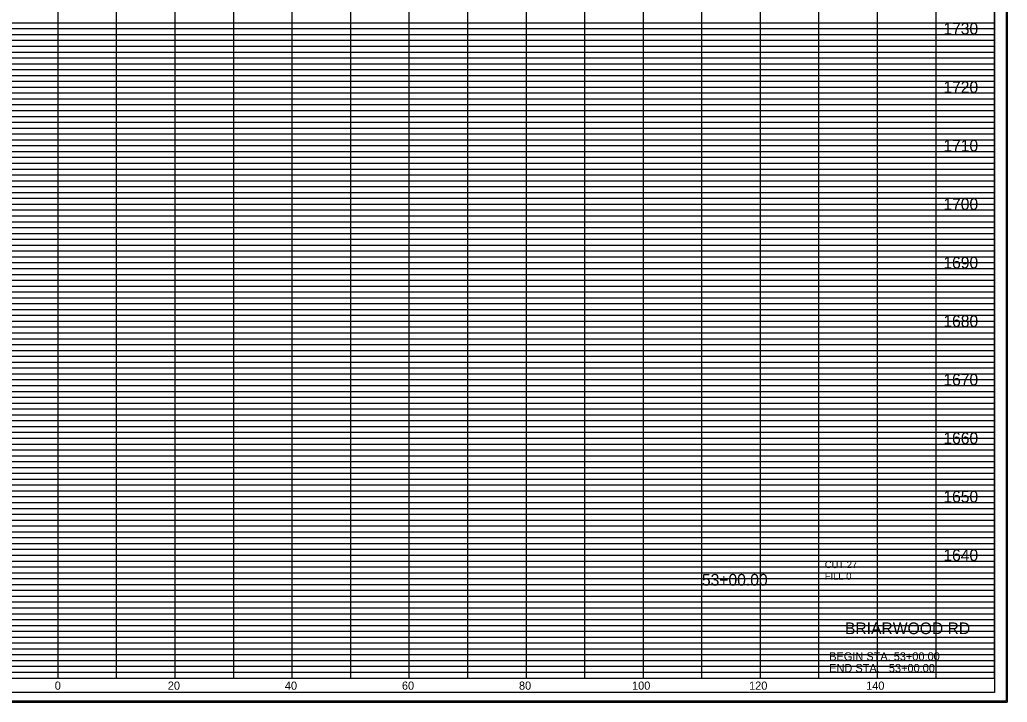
# Model space of a CAD drawing. Extents: x 980 to 2228, y 978 to 2394.
# Drawn here: x 1153.4 to 1322.2, y 1535.9 to 1652.5 of the extents above; entities that cross this region are included whole.
import ezdxf

# ---------------------------------------------------------------- set-up
doc = ezdxf.new("R2010")
doc.units = 0
for name, color, linetype in [('DESIGN - SHEET - Corner Text', 7, 'Continuous'), ('DESIGN - SHEET - Light Grid', 7, 'Continuous'), ('DESIGN - SHEET - Linework', 7, 'Continuous'), ('DESIGN - SHEET - Plot Shape', 7, 'Continuous'), ('DESIGN - TYPICAL - Finished Grade and Subgrade', 7, 'Continuous'), ('DESIGN - TYPICAL - Text', 7, 'Continuous')]:
    doc.layers.add(name, color=color, linetype=linetype)

# ---------------------------------------------------------------- blocks, each defined once
blk = doc.blocks.new('XSTSHT')
at = {"layer": 'DESIGN - SHEET - Light Grid'}
for p, q in [((8, 11.2), (16, 11.2)), ((16, 11.2), (24, 11.2)), ((24, 11.2), (32, 11.2)), ((8, 11.1), (16, 11.1)), ((16, 11.1), (24, 11.1)), ((24, 11.1), (32, 11.1)), ((8, 10.9), (16, 10.9)), ((8, 10.8), (16, 10.8)), ((16, 10.9), (24, 10.9)), ((16, 10.8), (24, 10.8)), ((24, 10.9), (32, 10.9)), ((24, 10.8), (32, 10.8)), ((8, 10.7), (16, 10.7)), ((16, 10.7), (24, 10.7)), ((24, 10.7), (32, 10.7)), ((8, 10.6), (16, 10.6)), ((8, 10.5), (16, 10.5)), ((16, 10.6), (24, 10.6)), ((16, 10.5), (24, 10.5)), ((24, 10.6), (32, 10.6)), ((24, 10.5), (32, 10.5)), ((8, 10.4), (16, 10.4)), ((8, 10.3), (16, 10.3)), ((16, 10.4), (24, 10.4)), ((16, 10.3), (24, 10.3)), ((24, 10.4), (32, 10.4)), ((24, 10.3), (32, 10.3)), ((8, 10.2), (16, 10.2)), ((16, 10.2), (24, 10.2)), ((24, 10.2), (32, 10.2)), ((8, 10.1), (16, 10.1)), ((16, 10.1), (24, 10.1)), ((24, 10.1), (32, 10.1)), ((8, 9.9), (16, 9.9)), ((8, 9.8), (16, 9.8)), ((16, 9.9), (24, 9.9)), ((16, 9.8), (24, 9.8)), ((24, 9.9), (32, 9.9)), ((24, 9.8), (32, 9.8)), ((8, 9.7), (16, 9.7)), ((16, 9.7), (24, 9.7)), ((24, 9.7), (32, 9.7)), ((8, 9.6), (16, 9.6)), ((8, 9.5), (16, 9.5)), ((16, 9.6), (24, 9.6)), ((16, 9.5), (24, 9.5)), ((24, 9.6), (32, 9.6)), ((24, 9.5), (32, 9.5)), ((8, 9.4), (16, 9.4)), ((8, 9.3), (16, 9.3)), ((16, 9.4), (24, 9.4)), ((16, 9.3), (24, 9.3)), ((24, 9.4), (32, 9.4)), ((24, 9.3), (32, 9.3)), ((8, 9.2), (16, 9.2)), ((16, 9.2), (24, 9.2)), ((24, 9.2), (32, 9.2)), ((8, 9.1), (16, 9.1)), ((16, 9.1), (24, 9.1)), ((24, 9.1), (32, 9.1)), ((8, 8.9), (16, 8.9)), ((8, 8.8), (16, 8.8)), ((16, 8.9), (24, 8.9)), ((16, 8.8), (24, 8.8)), ((24, 8.9), (32, 8.9)), ((24, 8.8), (32, 8.8)), ((8, 8.7), (16, 8.7)), ((16, 8.7), (24, 8.7)), ((24, 8.7), (32, 8.7)), ((8, 8.6), (16, 8.6)), ((8, 8.5), (16, 8.5)), ((16, 8.6), (24, 8.6)), ((16, 8.5), (24, 8.5)), ((24, 8.6), (32, 8.6)), ((24, 8.5), (32, 8.5)), ((8, 8.4), (16, 8.4)), ((8, 8.3), (16, 8.3)), ((16, 8.4), (24, 8.4)), ((16, 8.3), (24, 8.3)), ((24, 8.4), (32, 8.4)), ((24, 8.3), (32, 8.3)), ((8, 8.2), (16, 8.2)), ((8, 8.1), (16, 8.1)), ((16, 8.2), (24, 8.2)), ((16, 8.1), (24, 8.1)), ((24, 8.2), (32, 8.2)), ((24, 8.1), (32, 8.1)), ((8, 7.9), (16, 7.9)), ((8, 7.8), (16, 7.8)), ((16, 7.9), (24, 7.9)), ((16, 7.8), (24, 7.8)), ((24, 7.9), (32, 7.9)), ((24, 7.8), (32, 7.8)), ((8, 7.7), (16, 7.7)), ((8, 7.6), (16, 7.6)), ((16, 7.7), (24, 7.7)), ((16, 7.6), (24, 7.6)), ((24, 7.7), (32, 7.7)), ((24, 7.6), (32, 7.6)), ((8, 7.5), (16, 7.5)), ((16, 7.5), (24, 7.5)), ((24, 7.5), (32, 7.5)), ((8, 7.4), (16, 7.4)), ((8, 7.3), (16, 7.3)), ((16, 7.4), (24, 7.4)), ((16, 7.3), (24, 7.3)), ((24, 7.4), (32, 7.4)), ((24, 7.3), (32, 7.3)), ((8, 7.2), (16, 7.2)), ((8, 7.1), (16, 7.1)), ((16, 7.2), (24, 7.2)), ((16, 7.1), (24, 7.1)), ((24, 7.2), (32, 7.2)), ((24, 7.1), (32, 7.1)), ((8, 6.9), (16, 6.9)), ((8, 6.8), (16, 6.8)), ((16, 6.9), (24, 6.9)), ((16, 6.8), (24, 6.8)), ((24, 6.9), (32, 6.9)), ((24, 6.8), (32, 6.8)), ((8, 6.7), (16, 6.7)), ((8, 6.6), (16, 6.6)), ((16, 6.7), (24, 6.7)), ((16, 6.6), (24, 6.6)), ((24, 6.7), (32, 6.7)), ((24, 6.6), (32, 6.6)), ((8, 6.5), (16, 6.5)), ((16, 6.5), (24, 6.5)), ((24, 6.5), (32, 6.5)), ((8, 6.4), (16, 6.4)), ((8, 6.3), (16, 6.3)), ((16, 6.4), (24, 6.4)), ((16, 6.3), (24, 6.3)), ((24, 6.4), (32, 6.4)), ((24, 6.3), (32, 6.3)), ((8, 6.2), (16, 6.2)), ((8, 6.1), (16, 6.1)), ((16, 6.2), (24, 6.2)), ((16, 6.1), (24, 6.1)), ((24, 6.2), (32, 6.2)), ((24, 6.1), (32, 6.1)), ((8, 5.9), (16, 5.9)), ((8, 5.8), (16, 5.8)), ((16, 5.9), (24, 5.9)), ((16, 5.8), (24, 5.8)), ((24, 5.9), (32, 5.9)), ((24, 5.8), (32, 5.8)), ((8, 5.7), (16, 5.7)), ((8, 5.6), (16, 5.6)), ((16, 5.7), (24, 5.7)), ((16, 5.6), (24, 5.6)), ((24, 5.7), (32, 5.7)), ((24, 5.6), (32, 5.6)), ((8, 5.5), (16, 5.5)), ((8, 5.4), (16, 5.4)), ((16, 5.5), (24, 5.5)), ((16, 5.4), (24, 5.4)), ((24, 5.5), (32, 5.5)), ((24, 5.4), (32, 5.4)), ((8, 5.3), (16, 5.3)), ((16, 5.3), (24, 5.3)), ((24, 5.3), (32, 5.3)), ((8, 5.2), (16, 5.2)), ((8, 5.1), (16, 5.1)), ((16, 5.2), (24, 5.2)), ((16, 5.1), (24, 5.1)), ((24, 5.2), (32, 5.2)), ((24, 5.1), (32, 5.1)), ((8, 4.9), (16, 4.9)), ((16, 4.9), (24, 4.9)), ((24, 4.9), (32, 4.9)), ((8, 4.8), (16, 4.8)), ((16, 4.8), (24, 4.8)), ((24, 4.8), (32, 4.8)), ((8, 4.7), (16, 4.7)), ((8, 4.6), (16, 4.6)), ((16, 4.7), (24, 4.7)), ((16, 4.6), (24, 4.6)), ((24, 4.7), (32, 4.7)), ((24, 4.6), (32, 4.6)), ((8, 4.5), (16, 4.5)), ((8, 4.4), (16, 4.4)), ((16, 4.5), (24, 4.5)), ((16, 4.4), (24, 4.4)), ((24, 4.5), (32, 4.5)), ((24, 4.4), (32, 4.4)), ((8, 4.3), (16, 4.3)), ((16, 4.3), (24, 4.3)), ((24, 4.3), (32, 4.3)), ((8, 4.2), (16, 4.2)), ((8, 4.1), (16, 4.1)), ((16, 4.2), (24, 4.2)), ((16, 4.1), (24, 4.1)), ((24, 4.2), (32, 4.2)), ((24, 4.1), (32, 4.1)), ((8, 3.9), (16, 3.9)), ((16, 3.9), (24, 3.9)), ((24, 3.9), (32, 3.9)), ((8, 3.8), (16, 3.8)), ((16, 3.8), (24, 3.8)), ((24, 3.8), (32, 3.8)), ((8, 3.7), (16, 3.7)), ((8, 3.6), (16, 3.6)), ((16, 3.7), (24, 3.7)), ((16, 3.6), (24, 3.6)), ((24, 3.7), (32, 3.7)), ((24, 3.6), (32, 3.6)), ((8, 3.5), (16, 3.5)), ((8, 3.4), (16, 3.4)), ((16, 3.5), (24, 3.5)), ((16, 3.4), (24, 3.4)), ((24, 3.5), (32, 3.5)), ((24, 3.4), (32, 3.4)), ((8, 3.3), (16, 3.3)), ((16, 3.3), (24, 3.3)), ((24, 3.3), (32, 3.3)), ((8, 3.2), (16, 3.2)), ((8, 3.1), (16, 3.1)), ((16, 3.2), (24, 3.2)), ((16, 3.1), (24, 3.1)), ((24, 3.2), (32, 3.2)), ((24, 3.1), (32, 3.1)), ((8, 2.9), (16, 2.9)), ((16, 2.9), (24, 2.9)), ((24, 2.9), (32, 2.9)), ((8, 2.8), (16, 2.8)), ((8, 2.7), (16, 2.7)), ((16, 2.8), (24, 2.8)), ((16, 2.7), (24, 2.7)), ((24, 2.8), (32, 2.8)), ((24, 2.7), (32, 2.7)), ((8, 2.6), (16, 2.6)), ((16, 2.6), (24, 2.6)), ((24, 2.6), (32, 2.6)), ((8, 2.5), (16, 2.5)), ((8, 2.4), (16, 2.4)), ((16, 2.5), (24, 2.5)), ((16, 2.4), (24, 2.4)), ((24, 2.5), (32, 2.5)), ((24, 2.4), (32, 2.4)), ((8, 2.3), (16, 2.3)), ((8, 2.2), (16, 2.2)), ((16, 2.3), (24, 2.3)), ((16, 2.2), (24, 2.2)), ((24, 2.3), (32, 2.3)), ((24, 2.2), (32, 2.2)), ((8, 2.1), (16, 2.1)), ((16, 2.1), (24, 2.1)), ((24, 2.1), (32, 2.1)), ((8, 1.9), (16, 1.9)), ((16, 1.9), (24, 1.9)), ((24, 1.9), (32, 1.9)), ((8, 1.8), (16, 1.8)), ((8, 1.7), (16, 1.7)), ((16, 1.8), (24, 1.8)), ((16, 1.7), (24, 1.7)), ((24, 1.8), (32, 1.8)), ((24, 1.7), (32, 1.7)), ((8, 1.6), (16, 1.6)), ((16, 1.6), (24, 1.6)), ((24, 1.6), (32, 1.6)), ((8, 1.5), (16, 1.5)), ((8, 1.4), (16, 1.4)), ((16, 1.5), (24, 1.5)), ((16, 1.4), (24, 1.4)), ((24, 1.5), (32, 1.5)), ((24, 1.4), (32, 1.4)), ((8, 1.3), (16, 1.3)), ((8, 1.2), (16, 1.2)), ((16, 1.3), (24, 1.3)), ((16, 1.2), (24, 1.2)), ((24, 1.3), (32, 1.3)), ((24, 1.2), (32, 1.2)), ((8, 1.1), (16, 1.1)), ((16, 1.1), (24, 1.1)), ((24, 1.1), (32, 1.1)), ((8, 0.9), (16, 0.9)), ((16, 0.9), (24, 0.9)), ((24, 0.9), (32, 0.9)), ((8, 0.8), (16, 0.8)), ((8, 0.7), (16, 0.7)), ((16, 0.8), (24, 0.8)), ((16, 0.7), (24, 0.7)), ((24, 0.8), (32, 0.8)), ((24, 0.7), (32, 0.7)), ((8, 0.6), (16, 0.6)), ((16, 0.6), (24, 0.6)), ((24, 0.6), (32, 0.6)), ((8, 0.5), (16, 0.5)), ((8, 0.4), (16, 0.4)), ((16, 0.5), (24, 0.5)), ((16, 0.4), (24, 0.4)), ((24, 0.5), (32, 0.5)), ((24, 0.4), (32, 0.4)), ((8, 0.3), (16, 0.3)), ((8, 0.2), (16, 0.2)), ((16, 0.3), (24, 0.3)), ((16, 0.2), (24, 0.2)), ((24, 0.3), (32, 0.3)), ((24, 0.2), (32, 0.2)), ((8, 0.1), (16, 0.1)), ((16, 0.1), (24, 0.1)), ((24, 0.1), (32, 0.1))]:
    blk.add_line(p, q, dxfattribs=at)
at = {"layer": 'DESIGN - SHEET - Linework'}
for p, q in [((32.217, 21.414), (32.217, -0.414)), ((16, 0), (16, 21)), ((17, 0), (17, 21)), ((18, 0), (18, 21)), ((19, 0), (19, 21)), ((20, 0), (20, 21)), ((21, 0), (21, 21)), ((22, 0), (22, 21)), ((23, 0), (23, 21)), ((24, 0), (24, 21)), ((25, 0), (25, 21)), ((26, 0), (26, 21)), ((27, 0), (27, 21)), ((28, 0), (28, 20)), ((29, 0), (29, 20)), ((30, 0), (30, 20)), ((31, 0), (31, 20)), ((0, 11), (32, 11)), ((0, 10), (32, 10)), ((0, 9), (32, 9)), ((0, 8), (32, 8)), ((0, 7), (32, 7)), ((0, 6), (32, 6)), ((0, 5), (32, 5)), ((0, 4), (32, 4)), ((0, 3), (32, 3)), ((0, 2), (32, 2)), ((0, 1), (32, 1)), ((-1.823, -0.414), (32.217, -0.414))]:
    blk.add_line(p, q, dxfattribs=at)
blk.add_lwpolyline([(0, 21), (0, 0), (32, 0), (32, 21), (0, 21)], dxfattribs=at)
at = {"layer": 'DESIGN - SHEET - Plot Shape'}
for points in [[(-1.803, 21.394), (32.197, 21.394), (32.197, -0.394), (-1.803, -0.394)], [(-0.85, 21), (32, 21), (32, -0.25), (-0.85, -0.25)]]:
    blk.add_lwpolyline(points, close=True, dxfattribs=at)

msp = doc.modelspace()

# ---------------------------------------------------------------- linework, layer by layer
at = {"layer": 'DESIGN - SHEET - Plot Shape'}
msp.add_lwpolyline([(991.5, 1750), (1320, 1750), (1320, 1537.5), (991.5, 1537.5)], close=True, dxfattribs=at)

# ---------------------------------------------------------------- block references
at = {"layer": 'DESIGN - TYPICAL - Finished Grade and Subgrade', "xscale": 10, "yscale": 10}
msp.add_blockref('XSTSHT', (1000, 1540), dxfattribs=at)

# ---------------------------------------------------------------- texts
at = {"layer": 'DESIGN - SHEET - Corner Text'}
for s, height, p in [('1730', 2, (1311.25, 1650)), ('1720', 2, (1311.25, 1640)), ('1710', 2, (1311.25, 1630)), ('1700', 2, (1311.25, 1620)), ('1690', 2, (1311.25, 1610)), ('1680', 2, (1311.25, 1600)), ('1670', 2, (1311.25, 1590)), ('1660', 2, (1311.25, 1580)), ('1650', 2, (1311.25, 1570)), ('1640', 2, (1311.25, 1560)), ('BRIARWOOD RD', 2, (1294.44, 1547.5)), ('BEGIN STA. 53+00.00', 1.4, (1291.75, 1543)), ('END STA.   53+00.00', 1.4, (1291.75, 1541)), ('0', 1.4, (1159.42, 1538)), ('0', 1.4, (1159.42, 1538)), ('20', 1.4, (1178.74, 1538)), ('40', 1.4, (1198.74, 1538)), ('60', 1.4, (1218.74, 1538)), ('80', 1.4, (1238.74, 1538)), ('100', 1.4, (1258.06, 1538)), ('120', 1.4, (1278.06, 1538)), ('140', 1.4, (1298.06, 1538))]:
    msp.add_text(s, height=height, dxfattribs=at).set_placement(p)
at = {"layer": 'DESIGN - TYPICAL - Text'}
for s, height, p in [('CUT 27', 1.2, (1291, 1558.79)), ('53+00.00', 2, (1270, 1555.79)), ('FILL 0', 1.2, (1291, 1556.79))]:
    msp.add_text(s, height=height, dxfattribs=at).set_placement(p)

doc.saveas('drawing.dxf')
